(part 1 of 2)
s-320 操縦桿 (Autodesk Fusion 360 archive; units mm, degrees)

design "s-320 操縦桿" references "基板取付用2連ボリューム B10kΩ"
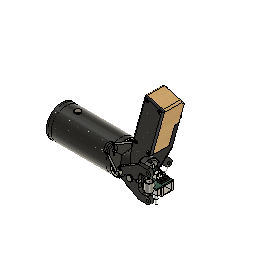
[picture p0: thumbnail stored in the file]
description: AWA10-30
part number: AWA10-30
description: SFBJ2.6-10
part number: SFBJ2.6-10
description: NPN1.6-10
part number: NPN1.6-10
description: HCLGN6-39.3_D
part number: HCLGN6-39.3_D
description: HCLGN6-39.3
part number: HCLGN6-39.3
description: NPN1-10
part number: NPN1-10
description: HCLGN4-8.2_D
part number: HCLGN4-8.2_D
description: HCLGN4-8.2
part number: HCLGN4-8.2
description: HCLGN6-16.0_D
part number: HCLGN6-16.0_D
parameter "d679" = 0.1
sketch "スケッチ1" plane through (0, 0, 0) normal (1, 0, 0) x axis (0, 1, 0)
  line L1 (0, -23.6) -> (0, 23.6)
  line L2 (-13.5196, -8.0798) -> (-45.6012, 45.6012)
  line L3 (8.0798, 13.5196) -> (-45.6012, 45.6012)
  line L4 (12.8728, -7.7) -> (12.8728, -6.1)
  line L5 (-12.8728, -7.7) -> (12.8728, -7.7)
  line L6 (-12.8728, -6.1) -> (-12.8728, -7.7)
  line L7 (12.8728, -6.1) -> (-12.8728, -6.1)
  line L8 (0, 0) -> (-26.7817, 26.7817)
  circle C1 centre (0, 0) radius 23.6
  circle C2 centre (0, 0) radius 23.5
  circle C3 centre (0, 0) radius 15
  circle C4 centre (0, 0) radius 15.75
  circle C5 centre (-26.7817, 26.7817) radius 6.5
  circle C6 centre (-26.7817, 26.7817) radius 3.5
  circle C7 centre (-26.7817, 26.7817) radius 2
  point P1 (0, 0)
  point P2 (0, 0)
  point P3 (0, 0)
  point P6 (0, 23.6)
  point P7 (0, -23.6)
  point P5 (0, 0)
  point P8 (0, 15.75)
  point P9 (0, 23.5)
  point P11 (-13.5196, -8.0798)
  point P17 (12.8728, -7.7)
  point P18 (-12.8728, -7.7)
  point P19 (-12.8728, -7.7)
  point P20 (12.8728, -7.7)
  point P13 (-26.7817, 26.7817)
  point P21 (-26.7817, 26.7817)
  point P4 (0, 0)
  point P22 (0, 0)
  point P16 (12.8728, -6.1)
  coincident P1 P2
  coincident P1 P3
  concentric C2 C3
  concentric C2 C4
  coincident C1 P6
  coincident C1 P7
  vertical L1
  coincident P5 L1
  coincident L1 P8
  coincident C4 P8
  coincident L1 P9
  coincident C2 P9
  tangent C4 L2
  tangent C4 L3
  equal L2 L3
  tangent L3 C5
  concentric C5 C6
  coincident C4 P11
  tangent L2 C5
  vertical L4
  horizontal L5
  vertical L6
  coincident C3 P17
  perpendicular L4 L7
  coincident C3 P18
  coincident P18 P19
  coincident P17 P20
  coincident P13 P21
  coincident P4 P22
  concentric C5 C7
  dimension "d7" diameter C2 = 47
  dimension "d8" distance C1 C2 = 0.1
  dimension "d9" diameter C3 = 30
  dimension "d10" distance C3 C4 = 0.75
  dimension "d22" diameter C6 = 7
  dimension "d23" distance C5 C6 = 3
  dimension "d27" angle P4 P9 P13 = 45
  dimension "d96" distance P16 P17 = 1.6
  dimension "d98" distance P4 L7 = 6.1
  dimension "d303" distance P21 P22 = 37.875
  dimension "d551" diameter C7 = 4
sketch "スケッチ4" plane through (0, 0, 0) normal (0, 1, 0) x axis (1, 0, 0)
  line L1 (-7, -23) -> (0, -23)
  line L2 (-7, -21.6024) -> (0, -21.6024)
  line L3 (-7, -16.6722) -> (-7, -23)
  line L4 (-6.5, -16.6722) -> (-7, -16.6722)
  line L5 (-6.5, -17.8066) -> (-6.5, -16.6722)
  line L6 (-6, -17.8066) -> (-6.5, -17.8066)
  line L7 (-6, -19.1283) -> (-6, -17.8066)
  line L8 (-6.5, -19.1283) -> (-6, -19.1283)
  line L9 (-6.5, -19.7045) -> (-6.5, -19.1283)
  line L10 (-6, -19.7045) -> (-6.5, -19.7045)
  line L11 (-6, -21.0261) -> (-6, -19.7045)
  line L12 (-7, -21.0261) -> (-6, -21.0261)
  line L13 (-7, -21.6024) -> (-7, -21.0261)
  line L14 (0, -16.6722) -> (0, -23)
  line L15 (-0.5, -16.6722) -> (0, -16.6722)
  line L16 (-0.5, -17.8066) -> (-0.5, -16.6722)
  line L17 (-1, -17.8066) -> (-0.5, -17.8066)
  line L18 (-1, -19.1283) -> (-1, -17.8066)
  line L19 (-0.5, -19.1283) -> (-1, -19.1283)
  line L20 (-0.5, -19.7045) -> (-0.5, -19.1283)
  line L21 (-1, -19.7045) -> (-0.5, -19.7045)
  line L22 (-1, -21.0261) -> (-1, -19.7045)
  line L23 (0, -21.0261) -> (-1, -21.0261)
  line L24 (0, -21.6024) -> (0, -21.0261)
  line L25 (-3.5, -21.6024) -> (-3.5, -23)
  line L26 (0, 23.6) -> (0, -23.6)
  line L27 (-7, -15.75) -> (-7, -21.6024)
  line L28 (0, -15.75) -> (-7, -15.75)
  point P28 (-3.5, -23)
  point P29 (-3.5, -21.6024)
  point P7 (0, -15.75)
  point P33 (0, -15.75)
  point P2 (0, -23)
  point P3 (-7, -23)
  point P6 (0, -23.5)
  horizontal L1
  horizontal L2
  equal L1 L2
  perpendicular L1 L3
  perpendicular L3 L4
  perpendicular L4 L5
  perpendicular L5 L6
  perpendicular L6 L7
  perpendicular L5 L8
  perpendicular L8 L9
  perpendicular L9 L10
  perpendicular L10 L11
  perpendicular L11 L12
  perpendicular L1 L14
  perpendicular L14 L15
  perpendicular L15 L16
  perpendicular L16 L17
  perpendicular L17 L18
  perpendicular L16 L19
  perpendicular L17 L20
  perpendicular L20 L21
  perpendicular L21 L22
  perpendicular L22 L23
  midpoint L1 P28
  midpoint L2 P29
  symmetric L4 L15 L25
  symmetric L6 L17 L25
  symmetric L5 L16 L25
  symmetric L7 L18 L25
  symmetric L8 L19 L25
  symmetric L9 L20 L25
  symmetric L11 L22 L25
  symmetric L10 L21 L25
  symmetric L12 L23 L25
  equal L6 L8
  equal L8 L10
  equal L7 L11
  equal L9 L13
  perpendicular L12 L13
  equal L4 L6
  perpendicular L2 L24
  collinear L24 L26
  perpendicular L2 L27
  coincident P7 P33
  perpendicular L27 L28
  dimension "d11" distance P2 P3 = 7
  dimension "d12" distance L7 L25 = 2.5
  dimension "d665" distance P2 P6 = 0.5
revolve "回転" sketch "スケッチ4" AlongAngle 360
extrude "押し出し5" new body sketch "スケッチ1" profile of C1 C2 C4 L2 L3 C5 C6 along normal blind 3
sketch "スケッチ6" plane through (0, 0, 0) normal (-1, 0, 0) x axis (0, -1, 0)
  line L1 (-23.2254, 1.0696) -> (-24.0956, -17.8259)
  line L2 (1.0696, -23.2254) -> (-17.8259, -24.0956)
  line L3 (-18.1019, -18.1019) -> (26.7817, 26.7817)
  circle C1 centre (-18.1019, -18.1019) radius 6
  circle C2 centre (0, 0) radius 23.25
  circle C3 centre (0, 0) radius 23
  circle C4 centre (-18.1019, -18.1019) radius 2
  circle C5 centre (0, 0) radius 23.5
  circle C6 centre (0, 0) radius 23.6
  circle C7 centre (0, 0) radius 21.0261
  point P4 (-24.0956, -17.8259)
  point P6 (-17.8259, -24.0956)
  point P5 (-23.2254, 1.0696)
  point P7 (1.0696, -23.2254)
  point P13 (0, 0)
  point P9 (-18.1019, -18.1019)
  point P12 (-18.1019, -18.1019)
  point P11 (26.7817, 26.7817)
  point P15 (26.7817, 26.7817)
  coincident C1 P4
  coincident C1 P6
  tangent C1 L2
  tangent C2 L2
  tangent C1 L1
  tangent C2 L1
  coincident C2 P5
  coincident C2 P7
  concentric C1 C4
  coincident L3 P13
  tangent C4 C6
  coincident P9 P12
  coincident P11 P15
  dimension "d281" diameter C1 = 12
  dimension "d282" diameter C4 = 4
extrude "押し出し11" new body sketch "スケッチ6" profile of C1 C2 L1 L2 C4 C6 along normal blind 5
sketch "スケッチ5" plane through (3, 0, 0) normal (1, 0, 0) x axis (0, 1, 0)
  line L1 (-23.4471, 32.3612) -> (8.0798, 13.5196)
  line L2 (-13.5196, -8.0798) -> (-32.3612, 23.4472)
  line L3 (-22.1855, 22.1855) -> (-31.247, 31.247)
  line L4 (8.074, 19.1147) -> (-24.2525, 32.7694)
  line L5 (-19.1147, -8.074) -> (-32.7694, 24.2525)
  line L6 (61.3359, -28.8089) -> (35.7796, -3.2527)
  line L7 (28.8089, -61.3359) -> (3.2527, -35.7796)
  line L8 (35.88, -54.2648) -> (54.2648, -35.88)
  line L9 (10.3238, -28.7085) -> (35.88, -54.2648)
  line L10 (28.7085, -10.3238) -> (10.3238, -28.7085)
  line L11 (54.2648, -35.88) -> (28.7085, -10.3238)
  line L12 (14.9765, -17.8049) -> (18.1019, -20.9304)
  line L13 (17.8049, -14.9765) -> (20.9304, -18.1019)
  line L14 (18.1019, -18.1019) -> (-26.7817, 26.7817)
  line L15 (-14.5382, 14.5382) -> (-1.3727, 15.6901)
  line L16 (-15.6901, 1.3727) -> (-14.5382, 14.5382)
  line L17 (14.5382, -14.5382) -> (1.3727, -15.6901)
  line L18 (14.5382, -14.5382) -> (15.6901, -1.3727)
  line L19 (13.4687, 15.7847) -> (35.7796, -3.2527)
  line L20 (-15.7847, -13.4687) -> (3.2527, -35.7796)
  arc A1 centre (-26.7817, 26.7817) radius 6.5 clockwise from (-32.3612, 23.4472) to (-23.4471, 32.3612)
  arc A2 centre (0, 0) radius 15.75 clockwise from (-13.5196, -8.0798) to (8.0798, 13.5196)
  circle C1 centre (-26.7817, 26.7817) radius 2
  circle C2 centre (-26.7817, 26.7817) radius 6.5
  circle C3 centre (0, 0) radius 15.75
  circle C4 centre (0, 0) radius 20.75
  circle C5 centre (32.3445, -57.8003) radius 5
  circle C6 centre (57.8003, -32.3445) radius 5
  circle C7 centre (18.1019, -18.1019) radius 2
  circle C8 centre (0, 0) radius 15
  circle C9 centre (16.3907, -16.3907) radius 2
  circle C10 centre (-26.7817, 26.7817) radius 3.5
  circle C11 centre (57.8003, -32.3445) radius 2
  circle C12 centre (32.3445, -57.8003) radius 2
  circle C13 centre (-26.7817, 26.7817) radius 3.5
  point P4 (-23.4471, 32.3612)
  point P11 (-22.1855, 22.1855)
  point P8 (-26.7817, 26.7817)
  point P1 (0, 0)
  point P13 (0, 0)
  point P14 (-24.2525, 32.7694)
  point P15 (8.074, 19.1147)
  point P17 (-19.1147, -8.074)
  point P16 (-32.7694, 24.2525)
  point P19 (61.3359, -28.8089)
  point P21 (28.8089, -61.3359)
  point P28 (18.1019, -18.1019)
  point P30 (18.1019, -18.1019)
  point P34 (17.8049, -14.9765)
  point P32 (14.9765, -17.8049)
  point P39 (-1.3727, 15.6901)
  point P40 (-14.5382, 14.5382)
  point P41 (-15.6901, 1.3727)
  point P42 (1.3727, -15.6901)
  point P43 (14.5382, -14.5382)
  point P44 (15.6901, -1.3727)
  point P33 (20.9304, -18.1019)
  point P31 (18.1019, -20.9304)
  point P24 (54.2648, -35.88)
  point P25 (35.88, -54.2648)
  point P49 (13.4687, 15.7847)
  point P50 (-15.7847, -13.4687)
  point P37 (16.3907, -16.3907)
  point P45 (0, 0)
  point P22 (32.3445, -57.8003)
  point P47 (57.8003, -32.3445)
  concentric C1 C2
  coincident P4 C2
  coincident C2 P11
  coincident P8 L3
  coincident P1 P13
  tangent C4 L4
  tangent C2 L4
  coincident C2 P14
  coincident C4 P15
  tangent C4 L5
  coincident C4 P17
  tangent C2 L5
  coincident C2 P16
  parallel L3 L6
  parallel L3 L7
  coincident P19 C6
  coincident P21 C5
  tangent L6 C6
  equal C5 C6
  equal L6 L7
  perpendicular L8 L9
  perpendicular L9 L10
  perpendicular L10 L11
  tangent C5 L9
  tangent C6 L11
  tangent L7 C5
  coincident P28 P30
  tangent C7 L12
  tangent C7 L13
  parallel L12 L14
  tangent L10 C7
  tangent L13 C9
  tangent L12 C9
  coincident P34 C9
  coincident P32 C9
  coincident C3 P39
  coincident L14 P40
  coincident C3 P41
  equal L15 L16
  tangent C3 L15
  coincident C3 P42
  coincident L14 P43
  tangent C3 L17
  coincident C3 P44
  tangent C3 L18
  equal L15 L18
  coincident L10 P33
  coincident L10 P31
  concentric C1 C10
  perpendicular L10 L12
  parallel L6 L11
  coincident C6 P24
  concentric C6 C11
  concentric C5 C12
  equal C11 C12
  coincident C5 P25
  equal L6 L11
  coincident C4 P49
  coincident C4 P50
  equal L19 L20
  tangent C4 L20
  tangent C4 L19
  parallel L12 L13
  dimension "d29" distance C3 C4 = 5
  dimension "d30" diameter C1 = 4
  dimension "d46" diameter C6 = 10
  dimension "d54" diameter C7 = 4
  dimension "d288" angle L15 L16 = 100
  dimension "d302" distance P37 P45 = 23.18
  dimension "d304" distance L8 P30 = 38.142
  dimension "d338" diameter C11 = 4
  dimension "d632" distance P22 P47 = 36
extrude "押し出し6" new body sketch "スケッチ5" profile of A1 C1 C2 L14 C10 along normal blind 2.5
extrude "押し出し7" add sketch "スケッチ5" profile of L1 A1 A2 C2 C3 C4 L4 L6 C6 L10 L11 L13 L14 C9 L15 L18 C11 L19 along normal blind 5
extrude "押し出し8" new body of existing geometry blind 2.5
extrude "押し出し9" add sketch "スケッチ5" profile of A1 L2 A2 C2 C3 C4 L5 L7 C5 L9 L10 L12 L14 C9 L16 L17 C12 L20 along normal blind 5
fillet "フィレット1" radius 5
work_plane "作業平面2" RotateAngle 0 RotateAngle 0
sketch "スケッチ14" plane through (0, 0, -6.1) normal (0, 0, 1) x axis (1, 0, 0)
  line L1 (-82.5, -12.8728) -> (59.5, -12.8728)
  line L2 (-82.5, 12.8728) -> (-82.5, -12.8728)
  line L3 (59.5, 12.8728) -> (-82.5, 12.8728)
  line L4 (59.5, -12.8728) -> (59.5, 12.8728)
  line L5 (9, -10.5) -> (-68, -10.5)
  line L6 (9, 10.5) -> (9, -10.5)
  line L7 (-68, 10.5) -> (9, 10.5)
  line L8 (-68, -10.5) -> (-68, 10.5)
  line L9 (9, 12.8728) -> (9, -12.8728)
  line L10 (5.75, 9) -> (-64.75, 9)
  line L11 (5.75, -9) -> (5.75, 9)
  line L12 (-64.75, -9) -> (5.75, -9)
  line L13 (-64.75, 9) -> (-64.75, -9)
  line L14 (-64.75, 10.5) -> (-64.75, 9)
  line L15 (-64.75, -10.5) -> (-64.75, -9)
  line L16 (5.75, 10.5) -> (5.75, 9)
  line L17 (5.75, -10.5) -> (5.75, -9)
  line L18 (-72.9, 2.5) -> (-68, 2.5)
  line L19 (-72.9, -2.5) -> (-72.9, 2.5)
  line L20 (-68, -2.5) -> (-72.9, -2.5)
  line L21 (-82.5, 4.75) -> (-72.9, 4.75)
  line L22 (-82.5, -4.75) -> (-82.5, 4.75)
  line L23 (-72.9, -4.75) -> (-82.5, -4.75)
  line L24 (-72.9, 4.75) -> (-72.9, -4.75)
  line L25 (-68, -2.5) -> (-68, 2.5)
  line L26 (13.9, -2.5) -> (9, -2.5)
  line L27 (13.9, 2.5) -> (13.9, -2.5)
  line L28 (9, 2.5) -> (13.9, 2.5)
  line L29 (9, -2.5) -> (9, 2.5)
  line L30 (22.5, 12.8728) -> (22.5, -12.8728)
  line L31 (36.5, -3.7272) -> (27, -3.7272)
  line L32 (36.5, 5.8728) -> (36.5, -3.7272)
  line L33 (27, 5.8728) -> (36.5, 5.8728)
  line L34 (27, -3.7272) -> (27, 5.8728)
  line L35 (59.5, 12.8728) -> (38.5, 12.8728)
  line L36 (59.5, -5.1272) -> (59.5, 12.8728)
  line L37 (38.5, -5.1272) -> (59.5, -5.1272)
  line L38 (38.5, 12.8728) -> (38.5, -5.1272)
  line L39 (59.5, 10.3728) -> (38.5, 10.3728)
  line L40 (38.5, -2.6272) -> (59.5, -2.6272)
  line L41 (24.5, 12.8728) -> (22.5, 12.8728)
  line L42 (22.5, -12.8728) -> (24.5, -12.8728)
  line L43 (22.5, 12.8728) -> (22.5, -12.8728)
  line L44 (12, 12.8728) -> (12, -12.8728)
  line L45 (51.3, -6.45) -> (59.5, -6.45)
  line L46 (51.3, -11.55) -> (51.3, -6.45)
  line L47 (59.5, -11.55) -> (51.3, -11.55)
  line L48 (47.5, -1.0872) -> (47.5, 8.8328)
  line L49 (41.6, -1.0872) -> (47.5, -1.0872)
  line L50 (41.6, 8.8328) -> (41.6, -1.0872)
  line L51 (47.5, 8.8328) -> (41.6, 8.8328)
  line L52 (46.7, -0.2872) -> (46.7, 8.0328)
  line L53 (42.4, -0.2872) -> (46.7, -0.2872)
  line L54 (42.4, 8.0328) -> (42.4, -0.2872)
  line L55 (46.7, 8.0328) -> (42.4, 8.0328)
  line L56 (46.7, 6.4328) -> (47.5, 6.4328)
  line L57 (46.7, 1.3128) -> (47.5, 1.3128)
  line L58 (51.2, -11.875) -> (51.2, -6.125)
  line L59 (36.25, -11.875) -> (51.2, -11.875)
  line L60 (36.25, -6.125) -> (36.25, -11.875)
  line L61 (51.2, -6.125) -> (36.25, -6.125)
  line L62 (56.5, 10.1228) -> (50.5, 10.1228)
  line L63 (56.5, 4.1228) -> (56.5, 10.1228)
  line L64 (50.5, 4.1228) -> (56.5, 4.1228)
  line L65 (50.5, 10.1228) -> (50.5, 4.1228)
  line L66 (56.5, 3.6228) -> (50.5, 3.6228)
  line L67 (56.5, -2.3772) -> (56.5, 3.6228)
  line L68 (50.5, -2.3772) -> (56.5, -2.3772)
  line L69 (50.5, 3.6228) -> (50.5, -2.3772)
  line L70 (37.05, -6.925) -> (37.05, -11.075)
  line L71 (50.4, -6.925) -> (37.05, -6.925)
  line L72 (50.4, -11.075) -> (50.4, -6.925)
  line L73 (37.05, -11.075) -> (50.4, -11.075)
  line L74 (50.5, 10.1228) -> (56.5, 4.1228)
  line L75 (56.5, -2.3772) -> (50.5, 3.6228)
  line L76 (38.15, -11.075) -> (38.15, -11.875)
  line L77 (49.3, -11.075) -> (49.3, -11.875)
  line L78 (39.7, -11.075) -> (39.7, -11.875)
  line L79 (47.75, -11.875) -> (47.75, -11.075)
  line L80 (46.7, 2.4628) -> (47.5, 2.4628)
  line L81 (47.5, 5.2828) -> (46.7, 5.2828)
  line L82 (59.5, -6.45) -> (59.5, -11.55)
  line L83 (59.5, -5.1272) -> (59.5, -12.8728)
  line L84 (51.2, -5.1272) -> (51.2, -12.8728)
  line L85 (38.5, 3.8728) -> (59.5, 3.8728)
  line L86 (56.5, 4.1228) -> (56.5, 3.6228)
  line L87 (51.2, -9) -> (51.3, -9)
  circle C1 centre (53.5, 7.1228) radius 1.7
  circle C2 centre (53.5, 0.6228) radius 1.7
  circle C3 centre (51.25, -9) radius 2.65
  point P6 (0, -12.8728)
  point P7 (0, 12.8728)
  point P13 (9, -12.8728)
  point P14 (9, 12.8728)
  point P19 (-64.75, 10.5)
  point P20 (-64.75, -10.5)
  point P21 (5.75, 10.5)
  point P22 (5.75, -10.5)
  point P31 (9, -2.5)
  point P35 (22.5, -12.8728)
  point P36 (22.5, 12.8728)
  point P45 (38.5, 10.3728)
  point P46 (59.5, 10.3728)
  point P47 (59.5, -2.6272)
  point P48 (38.5, -2.6272)
  point P50 (24.5, -12.8728)
  point P52 (12, -12.8728)
  point P53 (12, 12.8728)
  point P64 (47.5, 6.4328)
  point P65 (46.7, 6.4328)
  point P66 (47.5, 1.3128)
  point P67 (46.7, 1.3128)
  point P80 (43.725, -6.125)
  point P81 (53.5, 7.1228)
  point P82 (53.5, 0.6228)
  point P87 (38.15, -11.875)
  point P88 (38.15, -11.075)
  point P89 (49.3, -11.875)
  point P90 (49.3, -11.075)
  point P91 (39.7, -11.875)
  point P92 (39.7, -11.075)
  point P93 (47.75, -11.075)
  point P94 (47.75, -11.875)
  point P95 (47.5, 2.4628)
  point P96 (46.7, 2.4628)
  point P97 (46.7, 5.2828)
  point P98 (47.5, 5.2828)
  point P102 (51.2, -12.8728)
  point P103 (51.2, -5.1272)
  point P104 (59.5, 3.8728)
  point P105 (38.5, 3.8728)
  point P106 (56.5, 3.8728)
  point P107 (47.5, 3.8728)
  point P108 (51.3, -9)
  point P109 (51.2, -9)
  point P99 (51.25, -9)
  point P10 (9, 10.5)
  point P11 (-68, 10.5)
  point P8 (-68, -10.5)
  point P29 (-82.5, -4.75)
  point P30 (-72.9, -4.75)
  point P28 (-82.5, 4.75)
  point P25 (-72.9, -2.5)
  point P26 (-68, -2.5)
  point P39 (36.5, 5.8728)
  point P40 (27, 5.8728)
  point P38 (36.5, -3.7272)
  point P42 (59.5, 12.8728)
  point P43 (59.5, -5.1272)
  point P41 (38.5, 12.8728)
  point P57 (47.5, -1.0872)
  point P58 (41.6, -1.0872)
  point P59 (41.6, 8.8328)
  point P69 (51.2, -11.875)
  point P70 (36.25, -11.875)
  point P71 (36.25, -6.125)
  point P72 (50.5, 10.1228)
  point P73 (56.5, 10.1228)
  point P75 (50.5, 4.1228)
  point P100 (59.5, -6.45)
  point P101 (59.5, -11.55)
  point P54 (51.3, -6.45)
  point P74 (56.5, 4.1228)
  point P77 (56.5, 3.6228)
  horizontal L1
  vertical L2
  horizontal L3
  vertical L4
  coincident L1 P6
  coincident L3 P7
  horizontal L5
  vertical L6
  horizontal L7
  vertical L8
  coincident L1 P13
  coincident L3 P14
  perpendicular L3 L9
  midpoint L6 L9
  horizontal L10
  vertical L11
  horizontal L12
  vertical L13
  coincident L7 P19
  perpendicular L7 L14
  coincident L5 P20
  perpendicular L5 L15
  coincident L7 P21
  perpendicular L7 L16
  coincident L5 P22
  perpendicular L5 L17
  horizontal L18
  vertical L19
  horizontal L20
  horizontal L21
  vertical L22
  horizontal L23
  vertical L24
  midpoint L19 L24
  perpendicular L20 L25
  midpoint L8 L25
  horizontal L26
  vertical L27
  horizontal L28
  vertical L29
  coincident L9 P31
  equal L25 L27
  equal L20 L26
  midpoint L9 L29
  coincident L1 P35
  coincident L3 P36
  perpendicular L3 L30
  horizontal L31
  vertical L32
  horizontal L33
  vertical L34
  horizontal L35
  vertical L36
  horizontal L37
  vertical L38
  coincident L38 P45
  coincident L36 P46
  perpendicular L36 L39
  coincident L36 P47
  coincident L38 P48
  perpendicular L38 L40
  horizontal L41
  horizontal L42
  vertical L43
  coincident L1 P50
  coincident L1 P52
  coincident L3 P53
  perpendicular L3 L44
  horizontal L45
  vertical L46
  horizontal L47
  coincident L48 P64
  coincident L52 P65
  perpendicular L52 L56
  coincident L48 P66
  coincident L52 P67
  perpendicular L52 L57
  horizontal L62
  vertical L63
  horizontal L64
  vertical L65
  horizontal L66
  vertical L67
  horizontal L68
  vertical L69
  equal L62 L66
  equal L65 L69
  midpoint L61 P80
  equal C1 C2
  midpoint P81 L74
  midpoint P82 L75
  coincident L59 P87
  coincident L73 P88
  perpendicular L73 L76
  coincident L59 P89
  coincident L73 P90
  perpendicular L73 L77
  coincident L59 P91
  coincident L73 P92
  perpendicular L73 L78
  coincident L73 P93
  coincident L59 P94
  perpendicular L59 L79
  coincident L48 P95
  coincident L52 P96
  perpendicular L52 L80
  coincident L52 P97
  coincident L48 P98
  perpendicular L48 L81
  perpendicular L47 L82
  collinear L3 L35
  collinear L4 L36
  midpoint L82 L83
  parallel L71 L73
  coincident L1 P102
  coincident L37 P103
  perpendicular L37 L84
  midpoint L58 L84
  collinear L58 L84
  parallel L52 L54
  midpoint L36 P104
  midpoint L38 P105
  collinear L63 L67
  midpoint L86 P106
  coincident L85 P106
  midpoint L48 P107
  coincident L85 P107
  midpoint L46 P108
  midpoint L84 P109
  midpoint P99 L87
  dimension "d100" distance P10 P11 = 77
  dimension "d101" distance P8 P11 = 21
  dimension "d111" distance P6 L9 = 9
  dimension "d112" distance L7 L10 = 1.5
  dimension "d113" distance L5 L12 = 1.5
  dimension "d114" distance L6 L11 = 3.25
  dimension "d115" distance L8 L13 = 3.25
  dimension "d129" distance P29 P30 = 9.6
  dimension "d130" distance P28 P29 = 9.5
  dimension "d131" distance P25 P26 = 4.9
  dimension "d132" distance L18 L20 = 5
  dimension "d141" distance L9 L30 = 13.5
  dimension "d157" distance P39 P40 = 9.5
  dimension "d158" distance P38 P39 = 9.6
  dimension "d159" distance P42 P43 = 18
  dimension "d160" distance P41 P42 = 21
  dimension "d161" distance L37 L40 = 2.5
  dimension "d162" distance L35 L39 = 2.5
  dimension "d186" distance L9 L44 = 3
  dimension "d195" distance P57 P58 = 5.9
  dimension "d196" distance P58 P59 = 9.92
  dimension "d197" distance L51 L55 = 0.8
  dimension "d198" distance L48 L52 = 0.8
  dimension "d199" distance L49 L53 = 0.8
  dimension "d200" distance L50 L54 = 0.8
  dimension "d233" distance L3 L33 = 7
  dimension "d447" distance L51 L56 = 2.4
  dimension "d448" distance L49 L57 = 2.4
  dimension "d553" distance P69 P70 = 14.95
  dimension "d554" distance P70 P71 = 5.75
  dimension "d555" distance P72 P73 = 6
  dimension "d556" distance P72 P75 = 6
  dimension "d559" distance L60 L70 = 0.8
  dimension "d560" distance L61 L71 = 0.8
  dimension "d561" distance L58 L72 = 0.8
  dimension "d562" distance L59 L73 = 0.8
  dimension "d563" diameter C1 = 3.4
  dimension "d564" distance L60 L76 = 1.9
  dimension "d565" distance L58 L77 = 1.9
  dimension "d567" distance L58 L79 = 3.45
  dimension "d568" distance L60 L78 = 3.45
  dimension "d569" distance L49 L80 = 3.55
  dimension "d570" distance L51 L81 = 3.55
  dimension "d571" diameter C3 = 5.3
  dimension "d634" distance P100 P101 = 5.1
  dimension "d635" distance P54 P100 = 8.2
  dimension "d637" distance L32 L38 = 2
  dimension "d638" distance L36 L67 = 3
  dimension "d639" distance L48 L69 = 3
  dimension "d640" distance P74 P77 = 0.5
  dimension "d641" distance L46 L84 = 0.1
  dimension "d695" distance L30 L34 = 4.5
extrude "押し出し22" new body sketch "スケッチ14" profile of L1 L2 L3 L4 L5 L6 L7 L8 L9 to an object
sketch "スケッチ15" plane through (0, 12.8728, 0) normal (0, 1, 0) x axis (-1, 0, 0)
  line L1 (82.5, -7.7) -> (-59.5, -7.7)
  line L2 (82.5, -6.1) -> (82.5, -7.7)
  line L3 (-59.5, -6.1) -> (82.5, -6.1)
  line L4 (-59.5, -7.7) -> (-59.5, -6.1)
  line L5 (-9, 0) -> (-21, 0)
  line L6 (-9, -6.1) -> (-9, 0)
  line L7 (-21, -6.1) -> (-9, -6.1)
  line L8 (-21, 0) -> (-21, -6.1)
  line L9 (0, 0) -> (-9, 0)
  circle C1 centre (-15, 0) radius 3.25
  circle C2 centre (-15, 0) radius 6
  point P8 (-9, -6.1)
  point P10 (-9, -6.1)
  point P11 (-15, 0)
  point P7 (-9, 0)
  point P9 (-21, -6.1)
  point P13 (-21, -6.1)
  point P15 (0, 0)
  point P6 (-21, 0)
  horizontal L5
  vertical L6
  horizontal L7
  vertical L8
  coincident P8 P10
  midpoint L5 P11
  concentric C1 C2
  coincident P7 C2
  coincident P9 P13
  perpendicular L6 L9
  coincident L9 P15
  dimension "d107" diameter C1 = 6.5
  dimension "d108" distance P6 P7 = 12
extrude "押し出し24" new body sketch "スケッチ14" profile of L10 L11 L12 L13 along normal blind 1
extrude "押し出し25" add sketch "スケッチ14" profile of L5 L7 L10 L12 L14 L15 L16 L17 along normal blind 11
extrude "押し出し26" add sketch "スケッチ14" profile of L5 L6 L7 L8 L9 L11 L13 L14 L15 L16 L17 along normal blind 20.3
sketch "スケッチ16" plane through (-64.75, 0, 0) normal (1, 0, 0) x axis (0, 1, 0)
  line L1 (-9, 4.9) -> (-10.5, 4.9)
  line L2 (-9, -5.1) -> (-9, 4.9)
  line L3 (9, -5.1) -> (-9, -5.1)
  line L4 (9, 4.9) -> (9, -5.1)
  line L5 (10.5, 4.9) -> (9, 4.9)
  line L6 (10.5, 14.2) -> (10.5, 4.9)
  line L7 (-10.5, 14.2) -> (10.5, 14.2)
  line L8 (-10.5, 4.9) -> (-10.5, 14.2)
  line L9 (-5.5, 14.2) -> (-10.5, 4.9)
  line L10 (5.5, 14.2) -> (10.5, 4.9)
  point P2 (-10.5, 4.9)
  point P10 (-10.5, 4.9)
  point P11 (-5.5, 14.2)
  point P7 (10.5, 4.9)
  point P12 (10.5, 4.9)
  point P13 (5.5, 14.2)
  coincident P2 P10
  coincident L7 P11
  coincident P7 P12
  coincident L7 P13
  equal L9 L10
  dimension "d122" distance P11 P13 = 11
extrude "押し出し27" cut sketch "スケッチ16" profile of L6 L7 L8 L9 L10 no distance stored
fillet "フィレット2" radius 2
extrude "押し出し28" add sketch "スケッチ14" profile of L6 L8 L9 L18 L19 L20 L24 L25 L26 L27 L28 L29 along normal blind 1
component_insert "コンポーネントの挿入14"
extrude "押し出し30" new body sketch "スケッチ15" profile of L3 L5 L6 L7 L8 C1 C2 to an object
extrude "押し出し31" cut sketch "スケッチ14" profile of L6 L9 L26 L27 L28 L29 L44 along normal blind 2
extrude "押し出し35" new body sketch "スケッチ1" profile of C3 C4 to an object
extrude "押し出し36" new body sketch "スケッチ1" profile of C1 C2 L2 L3 C5 to an object
extrude "押し出し39" new body sketch "スケッチ5" profile of C7 to an object Side2Offset 0
extrude "押し出し40" sketch "スケッチ14" profile of L3 L4 L35 L36 L37 L38 L39 L40 blind -11 bodies "ESP32"
extrude "押し出し41" sketch "スケッチ14" profile of L3 L4 L35 L36 L37 L38 L39 L40 L48 L49 L50 L51 L52 L53 L54 L55 L56 L57 L62 L63 L64 L65 L66 L67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 blind -1
sketch "スケッチ17" plane through (-97.5, 0, 0) normal (-1, 0, 0) x axis (0, -1, 0)
  line L1 (2.5981, -1.5) -> (-2.5981, -1.5)
  circle C1 centre (0, 0) radius 23.5
  circle C2 centre (0, 0) radius 23.6
  circle C3 centre (0, 0) radius 23
  circle C4 centre (0, 0) radius 23.5
  circle C5 centre (0, 0) radius 3
  arc A1 centre (0, 0) radius 3 clockwise from (-2.5981, -1.5) to (2.5981, -1.5)
  circle C6 centre (0, 0) radius 23
  point P1 (0, 0)
  point P3 (0, 0)
  point P7 (-2.5981, -1.5)
  point P9 (-2.5981, -1.5)
  point P6 (2.5981, -1.5)
  point P10 (2.5981, -1.5)
  coincident P1 P3
  concentric C3 C5
  equal C5 A1
  horizontal L1
  coincident P7 P9
  coincident P6 P10
  equal C3 C6
extrude "押し出し42" sketch "スケッチ17" profile of C3 C5 A1 L1 C6 blind 5
extrude "押し出し46" sketch "スケッチ14" profile of L4 L45 L46 L47 blind -8.2
sketch "スケッチ18" plane through (0, 0, -15.9) normal (0, 0, -1) x axis (-1, 0, 0)
  line L1 (-51.3, -11.55) -> (-59.5, -11.55)
  line L2 (-59.5, -11.55) -> (-59.5, -6.45)
  line L3 (-59.5, -6.45) -> (-51.3, -6.45)
  line L4 (-51.3, -6.45) -> (-51.3, -11.55)
  line L5 (-59.5, -11.55) -> (-59.5, -11.55)
  line L6 (-51.3, -6.45) -> (-59.5, -11.55)
  circle C1 centre (-55.4, -9) radius 2.35
  circle C2 centre (-55.4, -9) radius 1.85
  circle C3 centre (-55.4, -9) radius 1.05
  point P4 (-59.5, -11.55)
  point P7 (-59.5, -11.55)
  point P2 (-59.5, -11.55)
  point P8 (-59.5, -11.55)
  point P13 (-59.5, -11.55)
  point P12 (-51.3, -6.45)
  point P14 (-51.3, -6.45)
  point P9 (-55.4, -9)
  coincident P4 P7
  coincident P2 P8
  concentric C1 C2
  concentric C2 C3
  coincident P4 P13
  coincident P12 P14
  midpoint P9 L6
  dimension "d216" diameter C1 = 4.7
  dimension "d217" distance C1 C2 = 0.5
  dimension "d220" diameter C3 = 2.1
extrude "押し出し50" add sketch "スケッチ18" profile of C1 C2 blind 5.8
extrude "押し出し51" add sketch "スケッチ18" profile of C3 blind 15
extrude "押し出し47" new body sketch "スケッチ14" profile of L48 L49 L50 L51 L52 L53 L54 L55 L56 L57 L80 L81 along normal blind 7.1 bodies "XH"
extrude "押し出し48" add sketch "スケッチ14" profile of L52 L53 L54 L55 along normal blind 1
extrude "押し出し49" add sketch "スケッチ14" profile of L48 L49 L50 L51 L52 L53 L54 L55 L56 L57 L80 L81 along normal blind 3.2
extrude "押し出し110" sketch "スケッチ14" profile of L58 L59 L60 L61 L70 L71 L72 L73 L76 L77 L78 L79 blind -7.1 bodies "XH3"
extrude "押し出し111" sketch "スケッチ14" profile of L59 L73 L76 L77 L78 L79 blind -3.2
extrude "押し出し112" sketch "スケッチ14" profile of L58 L59 L60 L61 L70 L71 L72 L73 L76 L77 L78 L79 blind -1
extrude "押し出し113" new body sketch "スケッチ14" profile of L62 L63 L64 L65 L66 L67 L68 L69 C1 C2 along normal blind 2.95
extrude "押し出し114" sketch "スケッチ14" profile of C1 C2 blind 5
extrude "押し出し115" new body sketch "スケッチ14" profile of L64 L66 C1 C2 C3 along normal blind 8.7 bodies "LED"
fillet "フィレット5" radius 2.5
fillet "フィレット3" radius 1
component_insert "コンポーネントの挿入23"
position "位置5"
work_plane "作業平面4" AlongDistance 1
extrude "押し出し52" add sketch "スケッチ1" profile of C3 C4 to an object
extrude "押し出し98" cut of existing geometry blind -2
extrude "押し出し70" cut sketch "スケッチ15" profile of L5 C1 no distance stored
extrude "押し出し56" new body sketch "スケッチ15" profile of L5 C1 along normal blind 3 and against normal blind 42
sketch "スケッチ19" plane through (0, 15.8728, 0) normal (0, 1, 0) x axis (-1, 0, 0)
  circle C1 centre (-15, 0) radius 3.25
  circle C2 centre (-15, 0) radius 4.5
  concentric C1 C2
  dimension "d241" diameter C2 = 9
extrude "押し出し57" add sketch "スケッチ19" along normal blind 1.5
sketch "スケッチ25" plane through (36, 0, 0) normal (1, 0, 0) x axis (0, 1, 0)
  line L1 (-8.7272, -6.1) -> (-8.7272, 12.1999)
  line L2 (-13.7036, -6.1) -> (-8.7272, -6.1)
  line L3 (-5.1272, -6.1) -> (12.8728, -6.1)
  line L4 (-3.7272, 5.2) -> (-3.7272, -6.1)
  circle C1 centre (0, 0) radius 15
  point P4 (-13.7036, -6.1)
  point P2 (-8.7272, 12.1999)
  vertical L1
  perpendicular L1 L2
  coincident P4 C1
  coincident P2 C1
  collinear L2 L3
  dimension "d314" distance L1 L4 = 5
extrude "押し出し69" new body sketch "スケッチ25" profile of L1 L2 C1 to an object offset 3
sketch "スケッチ26" plane through (0, -8.7272, 0) normal (0, 1, 0) x axis (-1, 0, 0)
  line L1 (-24, 12.1999) -> (-24, -6.1)
  line L2 (-36, 12.1999) -> (-24, 12.1999)
  line L3 (-36, -6.1) -> (-36, 12.1999)
  line L4 (-24, -6.1) -> (-36, -6.1)
  line L5 (-30.25, 3.25) -> (-36, 3.25)
  line L6 (-36, -3.25) -> (-30.25, -3.25)
  line L7 (-36, -6.1) -> (-36, 12.1999)
  circle C1 centre (-30.25, 0) radius 3.25
  arc A1 centre (-30.25, 0) radius 3 clockwise from (-32.8481, -1.5) to (-27.6519, -1.5)
  point P10 (-36, 3.25)
  point P11 (-30.25, 3.25)
  point P13 (-36, -3.25)
  point P12 (-30.25, -3.25)
  concentric C1 A1
  perpendicular L3 L5
  perpendicular L3 L6
  coincident P10 L7
  coincident C1 P11
  coincident P13 L7
  coincident C1 P12
  tangent C1 L6
  tangent C1 L5
  dimension "d730" diameter C1 = 6.5
extrude "押し出し71" cut sketch "スケッチ26" profile of C1 A1 blind 0
extrude "押し出し120" cut sketch "スケッチ26" profile of L3 C1 A1 L5 L6 L7 no distance stored
work_plane "作業平面3" AlongDistance -17.75
sketch "スケッチ27" plane through (0, -17.75, 0) normal (0, 1, 0) x axis (1, 0, 0)
  line L1 (55.667, -23) -> (42.417, -23)
  line L2 (42.417, -13) -> (55.667, -13)
  line L3 (55.667, 13) -> (42.417, 13)
  line L4 (55.667, 23) -> (42.417, 23)
  line L5 (42.417, 13) -> (42.417, -13)
  line L6 (11.9691, -5.1782) -> (42.417, -23)
  line L7 (11.9691, 5.1782) -> (42.417, 23)
  line L8 (27.7604, -2.0891) -> (26.0074, 0)
  line L9 (34.4926, 0) -> (32.7396, -2.0891)
  line L10 (26.0074, 0) -> (27.7604, 2.0891)
  line L11 (34.4926, 0) -> (32.7396, 2.0891)
  line L12 (42.417, 0) -> (21, 0)
  line L13 (39.583, -2) -> (42.417, -2)
  line L14 (39.583, 2) -> (42.417, 2)
  line L15 (40.9088, 4.9758) -> (30.8401, 5.9709)
  line L16 (30.8401, -5.9709) -> (40.9088, -4.9758)
  line L17 (46.528, -114.8261) -> (26.4851, -42.5538)
  line L18 (75.4369, -106.8089) -> (46.528, -114.8261)
  line L19 (55.394, -34.5366) -> (75.4369, -106.8089)
  line L20 (26.4851, -42.5538) -> (55.394, -34.5366)
  line L21 (30.25, 0) -> (60.9824, -110.8175)
  line L22 (24.2583, -0.3159) -> (26.4851, -42.5538)
  line L23 (35.5486, 2.8152) -> (55.394, -34.5366)
  line L24 (19.2306, 10.0286) -> (30.25, 0)
  line L25 (15.6926, 3.1753) -> (30.25, 0)
  line L26 (28.0686, 16.8936) -> (35.5486, 2.8152)
  circle C1 centre (40.417, 0) radius 2
  circle C2 centre (15, 0) radius 6
  circle C3 centre (55.667, -18) radius 5
  circle C4 centre (55.667, 18) radius 5
  circle C5 centre (39.583, 0) radius 2
  circle C6 centre (30.25, 0) radius 3.25
  circle C7 centre (30.25, 0) radius 3.25
  circle C8 centre (55.667, -18) radius 2
  circle C9 centre (55.667, 18) radius 2
  circle C10 centre (40.417, 0) radius 5
  circle C11 centre (30.25, 0) radius 6
  circle C12 centre (15, 0) radius 3.25
  circle C13 centre (15, 0) radius 3.25
  circle C14 centre (8.7979, -1.4348) radius 15.5
  circle C15 centre (23.0532, 14.2288) radius 5.6793
  point P14 (11.9691, -5.1782)
  point P15 (11.9691, 5.1782)
  point P25 (21, 0)
  point P26 (42.417, 0)
  point P7 (55.667, -23)
  point P8 (55.667, -13)
  point P11 (55.667, 13)
  point P13 (55.667, 23)
  point P2 (40.417, 0)
  point P24 (39.583, 0)
  point P18 (32.7396, -2.0891)
  point P22 (32.7396, 2.0891)
  point P20 (27.7604, 2.0891)
  point P17 (27.7604, -2.0891)
  point P16 (26.0074, 0)
  point P21 (26.0074, 0)
  point P19 (34.4926, 0)
  point P23 (34.4926, 0)
  point P3 (15, 0)
  point P29 (15, 0)
  point P30 (42.417, -2)
  point P32 (42.417, 2)
  point P31 (39.583, -2)
  point P33 (39.583, 2)
  point P38 (30.8401, 5.9709)
  point P39 (40.9088, 4.9758)
  point P40 (40.9088, -4.9758)
  point P41 (30.8401, -5.9709)
  point P46 (60.9824, -110.8175)
  point P27 (30.25, 0)
  point P47 (30.25, 0)
  point P48 (24.2583, -0.3159)
  point P49 (35.5486, 2.8152)
  point P53 (15.6926, 3.1753)
  point P52 (19.2306, 10.0286)
  point P56 (35.5486, 2.8152)
  point P57 (28.0686, 16.8936)
  point P4 (55.667, -18)
  point P42 (26.4851, -42.5538)
  point P45 (55.394, -34.5366)
  point P37 (30.25, 0)
  point P34 (55.667, -18)
  point P35 (55.667, 18)
  horizontal L1
  horizontal L2
  horizontal L3
  horizontal L4
  coincident C2 P14
  coincident C2 P15
  parallel L9 L10
  coincident C2 P25
  coincident L5 P26
  horizontal L12
  tangent C3 L1
  tangent C3 L2
  tangent C4 L3
  tangent C4 L4
  equal C3 C4
  coincident C3 P7
  coincident C3 P8
  coincident C4 P11
  coincident C4 P13
  vertical L5
  tangent C1 L5
  midpoint L5 P26
  coincident P2 L12
  coincident P24 L12
  equal C1 C5
  concentric C6 C7
  equal C6 C7
  coincident P18 C6
  coincident P22 C6
  coincident P20 C6
  coincident P17 C6
  coincident P16 P21
  coincident P21 L12
  coincident P19 P23
  coincident P19 L12
  tangent L8 C6
  tangent L9 C6
  tangent L11 C6
  tangent L10 C6
  equal L8 L9
  coincident P3 P29
  equal L1 L2
  equal L2 L3
  equal L3 L4
  equal L6 L7
  coincident L5 P30
  coincident L5 P32
  coincident C5 P31
  coincident C5 P33
  tangent C1 L14
  tangent C5 L14
  tangent C1 L13
  tangent C5 L13
  tangent C2 L6
  concentric C3 C8
  concentric C4 C9
  concentric C1 C10
  concentric C6 C11
  coincident C11 P38
  coincident C10 P39
  coincident C10 P40
  coincident C11 P41
  tangent C10 L15
  tangent C10 L16
  tangent C11 L16
  tangent C11 L15
  perpendicular L17 L18
  perpendicular L18 L19
  perpendicular L19 L20
  midpoint L18 P46
  coincident P27 P47
  perpendicular L18 L21
  tangent C11 L22
  tangent C11 L23
  coincident C11 P48
  coincident C11 P49
  concentric C2 C12
  equal C12 C13
  equal C8 C9
  coincident C13 P53
  tangent C13 L25
  coincident C12 P53
  equal L24 L25
  coincident P52 C14
  tangent C11 C14
  tangent L24 C14
  coincident C11 P56
  coincident C15 P57
  tangent C15 L26
  tangent C14 C15
  coincident P52 C15
  tangent C11 L26
  collinear L23 L26
  dimension "d322" angle L8 L10 = 100
  dimension "d324" distance L1 L2 = 10
  dimension "d329" diameter C1 = 4
  dimension "d334" distance P2 P27 = 10.167
  dimension "d335" distance P24 P27 = 9.333
  dimension "d336" distance P2 P4 = 15.25
  dimension "d337" diameter C2 = 12
  dimension "d340" diameter C8 = 4
  dimension "d342" diameter C10 = 10
  dimension "d343" diameter C11 = 12
  dimension "d344" distance P42 P45 = 30
  dimension "d346" angle L12 L21 = 74.5
  dimension "d347" distance P37 L20 = 40
  dimension "d348" distance L18 L20 = 75
  dimension "d631" distance P34 P35 = 36
  dimension "d662" angle L24 L25 = 30
extrude "押し出し72" new body sketch "スケッチ27" profile of C2 C12 C13 against normal blind 2.5
extrude "押し出し73" new body sketch "スケッチ27" profile of C2 C3 L1 L2 L5 L6 L8 L9 C5 L12 C6 C7 L13 C8 C10 C11 L16 L21 L22 L23 C14 against normal blind 5
extrude "押し出し74" new body of existing geometry blind 2.5
extrude "押し出し75" new body sketch "スケッチ27" profile of C2 C4 L3 L4 L5 L7 L10 L11 C5 L12 C6 C7 L14 C9 C10 C11 L15 L23 C14 C15 L26 against normal blind 5
combine "結合1"
combine "結合2"
fillet "フィレット4" radius 5
work_plane "作業平面5" AlongDistance 17.75
sketch "スケッチ28" plane through (0, 17.75, 0) normal (0, 1, 0) x axis (1, 0, 0)
extrude "押し出し76" new body sketch "スケッチ27" profile of C1 L1 L2 L5 L6 L7 L8 L9 L10 L11 C5 L12 C6 C7 L13 L14 C10 C11 L15 L16 L17 L18 L19 L20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 along normal blind 2
extrude "押し出し77" sketch "スケッチ27" profile of L1 L2 L5 L6 L8 L9 L10 L11 L12 C6 C7 C10 C11 L16 L17 L18 L19 L20 L21 L22 L23 C14 blind -2
extrude "押し出し78" sketch "スケッチ27" profile of L17 L18 L19 L21 to an object
sketch "スケッチ45" plane through (42.5441, 0, -11.7985) normal (0.9636, 0, -0.2672) x axis (0, 1, 0)
  line L1 (15.75, 123.084) -> (15.75, 48.084)
  line L2 (-15.75, 123.084) -> (15.75, 123.084)
  line L3 (-15.75, 48.084) -> (-15.75, 123.084)
  line L4 (15.75, 48.084) -> (-15.75, 48.084)
  circle C1 centre (17.75, 123.084) radius 7.5
  point P6 (17.75, 123.084)
  point P7 (17.75, 123.084)
  coincident P6 P7
  dimension "d659" diameter C1 = 15
extrude "押し出し123" cut sketch "スケッチ45" profile of L1 L2 C1 to an object
extrude "押し出し80" cut of existing geometry to an object
sketch "スケッチ44" plane through (0, 17.75, 0) normal (0, 1, 0) x axis (-1, 0, 0)
  line L1 (-32.8481, -1.5) -> (-27.6519, -1.5)
  line L2 (-26.4851, 42.5538) -> (-24.2583, 0.3159)
  line L3 (-44.5237, 107.5988) -> (-26.4851, 42.5538)
  line L4 (-55.394, 34.5366) -> (-73.4326, 99.5817)
  line L5 (-35.5486, -2.8152) -> (-55.394, 34.5366)
  line L6 (-16.3279, -4.2996) -> (-30.25, 0)
  line L7 (-20.3429, -10.6846) -> (-30.25, 0)
  line L8 (-24.1533, -1.6763) -> (-24.2583, 0.3159)
  line L9 (-28.3449, -16.3735) -> (-35.5486, -2.8152)
  line L10 (-73.4326, 99.5817) -> (-44.5237, 107.5988)
  arc A1 centre (-30.25, 0) radius 3 clockwise from (-32.8481, -1.5) to (-27.6519, -1.5)
  arc A2 centre (-30.25, 0) radius 6 clockwise from (-24.2583, 0.3159) to (-35.5486, -2.8152)
  circle C1 centre (-15, 0) radius 4.5
  circle C2 centre (-9.8122, -0.9203) radius 14.3611
  circle C3 centre (-23.9731, -14.0507) radius 4.9506
  point P4 (-30.25, 0)
  point P11 (-30.25, 0)
  point P12 (-16.3279, -4.2996)
  point P5 (-24.2583, 0.3159)
  point P16 (-24.2583, 0.3159)
  point P17 (-24.1533, -1.6763)
  point P14 (-20.3429, -10.6846)
  point P19 (-35.5486, -2.8152)
  point P20 (-28.3449, -16.3735)
  coincident P4 P11
  tangent L6 C1
  coincident P12 C1
  tangent L2 C2
  tangent L7 C2
  coincident P5 P16
  tangent A2 L8
  coincident C2 P17
  tangent C2 L8
  equal L6 L7
  coincident P14 C2
  coincident P14 C3
  coincident A2 P19
  coincident C3 P20
  tangent C3 L9
  tangent A2 L9
  tangent L7 C3
  collinear L5 L9
  dimension "d655" angle L6 L7 = 30
extrude "押し出し122" add sketch "スケッチ44" profile of A2 C2 L8 C3 L9 to an object
extrude "押し出し81" new body sketch "スケッチ27" profile of C1 C5 L12 to an object Side2Offset 0
extrude "押し出し82" new body sketch "スケッチ26" profile of C1 A1 along normal blind 5 and against normal blind 16
sketch "スケッチ29" plane through (0, -24.7272, 0) normal (0, -1, 0) x axis (1, 0, 0)
  circle C1 centre (30.25, 0) radius 3.25
  circle C2 centre (30.25, 0) radius 4.5
  concentric C1 C2
  dimension "d382" diameter C2 = 9
extrude "押し出し83" add sketch "スケッチ29" along normal blind 1.5
sketch "スケッチ31" plane through (0, 17.75, 0) normal (0, 1, 0) x axis (-1, 0, 0)
  line L1 (-32.8481, -1.5) -> (-27.6519, -1.5)
  line L2 (-26.4851, 42.5538) -> (-24.1533, -1.6763)
  line L3 (-44.5237, 107.5988) -> (-26.4851, 42.5538)
  line L4 (-55.394, 34.5366) -> (-73.4326, 99.5817)
  line L5 (-28.3449, -16.3735) -> (-55.394, 34.5366)
  line L6 (-37.2076, 66.2501) -> (-46.2937, 99.0136)
  line L7 (-58.4075, 60.3709) -> (-37.2076, 66.2501)
  line L8 (-45.492, 96.1227) -> (-51.2738, 94.5193)
  line L9 (-43.8886, 90.3409) -> (-45.492, 96.1227)
  line L10 (-49.6704, 88.7375) -> (-43.8886, 90.3409)
  line L11 (-51.2738, 94.5193) -> (-49.6704, 88.7375)
  line L12 (-42.5524, 85.5228) -> (-48.3342, 83.9193)
  line L13 (-40.949, 79.741) -> (-42.5524, 85.5228)
  line L14 (-46.7307, 78.1375) -> (-40.949, 79.741)
  line L15 (-48.3342, 83.9193) -> (-46.7307, 78.1375)
  line L16 (-39.6128, 74.9228) -> (-45.3946, 73.3194)
  line L17 (-38.0093, 69.141) -> (-39.6128, 74.9228)
  line L18 (-43.7911, 67.5376) -> (-38.0093, 69.141)
  line L19 (-45.3946, 73.3194) -> (-43.7911, 67.5376)
  line L20 (-43.8886, 90.3409) -> (-51.2738, 94.5193)
  line L21 (-40.949, 79.741) -> (-48.3342, 83.9193)
  line L22 (-38.0093, 69.141) -> (-45.3946, 73.3194)
  line L23 (-30.25, 0) -> (-60.9824, 110.8175)
  line L24 (-75.4369, 106.8089) -> (-46.528, 114.8261)
  line L25 (-51.9082, 74.0555) -> (-61.4674, 71.4045)
  line L26 (-48.8483, 63.0219) -> (-51.9082, 74.0555)
  line L27 (-61.4674, 71.4045) -> (-58.4075, 60.3709)
  line L28 (-57.4439, 60.6381) -> (-60.5037, 71.6717)
  line L29 (-49.8119, 62.7547) -> (-52.8718, 73.7882)
  line L30 (-51.6826, 69.5001) -> (-59.3145, 67.3836)
  line L31 (-51.4153, 68.5364) -> (-59.0473, 66.4199)
  line L32 (-58.7923, 64.4152) -> (-57.7233, 60.5606)
  line L33 (-50.6014, 66.6867) -> (-58.7923, 64.4152)
  line L34 (-49.5325, 62.8322) -> (-50.6014, 66.6867)
  line L35 (-26.4851, 42.5538) -> (-55.394, 34.5366)
  line L36 (-35.5486, -2.8152) -> (-55.394, 34.5366)
  line L37 (-58.4075, 60.3709) -> (-67.4936, 93.1343)
  line L38 (-55.394, 34.5366) -> (-75.4369, 106.8089)
  line L39 (-24.2583, 0.3159) -> (-26.4851, 42.5538)
  line L40 (-54.6968, 65.5509) -> (-55.2313, 67.4782)
  line L41 (-58.7722, 84.1378) -> (-60.3756, 89.9196)
  line L42 (-64.554, 82.5344) -> (-58.7722, 84.1378)
  line L43 (-66.1574, 88.3162) -> (-64.554, 82.5344)
  line L44 (-60.3756, 89.9196) -> (-66.1574, 88.3162)
  line L45 (-58.7722, 84.1378) -> (-66.1574, 88.3162)
  line L46 (-46.2937, 99.0136) -> (-67.4936, 93.1343)
  line L47 (-56.5188, 60.8947) -> (-57.5877, 64.7492)
  line L48 (-51.806, 66.3526) -> (-50.737, 62.4981)
  line L49 (-26.4851, 42.5538) -> (-36.2207, 77.6593)
  line L50 (-26.4851, 42.5538) -> (-55.394, 34.5366)
  line L51 (-65.3219, 70.3355) -> (-61.4674, 71.4045)
  line L52 (-41.9803, 38.2566) -> (-48.8483, 63.0219)
  line L53 (-73.4326, 99.5817) -> (-44.5237, 107.5988)
  arc A1 centre (-30.25, 0) radius 3 clockwise from (-32.8481, -1.5) to (-27.6519, -1.5)
  circle C1 centre (-47.5812, 92.4301) radius 1.725
  circle C2 centre (-44.6416, 81.8301) radius 1.725
  circle C3 centre (-41.7019, 71.2302) radius 1.725
  circle C4 centre (-62.4648, 86.227) radius 1.725
  circle C5 centre (-59.181, 73.0763) radius 2.65
  arc A2 centre (-23.9731, -14.0507) radius 4.9506 clockwise from (-20.3429, -10.6846) to (-28.3449, -16.3735)
  arc A3 centre (-9.8122, -0.9203) radius 14.3611 clockwise from (-20.3429, -10.6846) to (-24.1533, -1.6763)
  point P24 (-47.5812, 92.4301)
  point P25 (-44.6416, 81.8301)
  point P26 (-41.7019, 71.2302)
  point P34 (-60.5037, 71.6717)
  point P35 (-57.4439, 60.6381)
  point P36 (-52.8718, 73.7882)
  point P38 (-59.3145, 67.3836)
  point P39 (-51.6826, 69.5001)
  point P40 (-59.0473, 66.4199)
  point P41 (-51.4153, 68.5364)
  point P45 (-49.5325, 62.8322)
  point P47 (-58.4075, 60.3709)
  point P54 (-58.4075, 60.3709)
  point P52 (-55.394, 34.5366)
  point P46 (-55.394, 34.5366)
  point P49 (-55.394, 34.5366)
  point P5 (-26.4851, 42.5538)
  point P48 (-26.4851, 42.5538)
  point P57 (-55.2313, 67.4782)
  point P58 (-54.6968, 65.5509)
  point P11 (-37.2076, 66.2501)
  point P53 (-37.2076, 66.2501)
  point P63 (-62.4648, 86.227)
  point P65 (-57.5877, 64.7492)
  point P68 (-51.806, 66.3526)
  point P69 (-36.2207, 77.6593)
  point P55 (-26.4851, 42.5538)
  point P70 (-26.4851, 42.5538)
  point P71 (-55.394, 34.5366)
  point P33 (-58.4075, 60.3709)
  point P42 (-57.7233, 60.5606)
  point P66 (-56.5188, 60.8947)
  point P67 (-50.737, 62.4981)
  point P37 (-49.8119, 62.7547)
  point P72 (-48.8483, 63.0219)
  point P73 (-65.3219, 70.3355)
  point P74 (-41.9803, 38.2566)
  point P13 (-45.492, 96.1227)
  point P14 (-43.8886, 90.3409)
  point P31 (-61.4674, 71.4045)
  point P32 (-51.9082, 74.0555)
  point P43 (-58.7923, 64.4152)
  point P44 (-50.6014, 66.6867)
  point P64 (-59.181, 73.0763)
  equal L11 L15
  equal L15 L19
  equal L12 L15
  equal L16 L19
  equal C1 C2
  equal C2 C3
  midpoint P24 L20
  midpoint P25 L21
  midpoint P26 L22
  coincident L25 P34
  coincident L7 P35
  coincident L25 P36
  coincident L28 P38
  coincident L29 P39
  perpendicular L29 L30
  coincident L28 P40
  coincident L29 P41
  perpendicular L29 L31
  perpendicular L32 L33
  coincident L7 P45
  perpendicular L6 L35
  equal L8 L9
  parallel L12 L14
  parallel L16 L18
  parallel L26 L27
  perpendicular L18 L37
  coincident P47 P54
  parallel L37 L38
  coincident L35 P52
  coincident P46 P49
  coincident P5 P48
  midpoint L31 P57
  midpoint L33 P58
  perpendicular L31 L40
  coincident P11 P53
  collinear L11 L15
  collinear L15 L19
  perpendicular L17 L18
  perpendicular L13 L14
  perpendicular L9 L10
  perpendicular L23 L42
  perpendicular L42 L43
  parallel L6 L41
  parallel L42 L44
  equal L10 L42
  equal L9 L41
  equal C1 C4
  midpoint P63 L45
  perpendicular L8 L11
  perpendicular L6 L46
  coincident L33 P65
  coincident L33 P68
  perpendicular L33 L48
  perpendicular L33 L47
  perpendicular L7 L37
  coincident L3 P69
  coincident P55 P70
  coincident P49 P71
  collinear L6 L13
  collinear L37 L43
  collinear L27 L37
  coincident L7 P33
  coincident L7 P42
  coincident L7 P66
  coincident L7 P67
  coincident L7 P37
  coincident L7 P72
  perpendicular L25 L37
  coincident L38 P73
  perpendicular L38 L51
  coincident L50 P74
  perpendicular L50 L52
  tangent L37 C5
  dimension "d386" distance L14 L16 = 5
  dimension "d387" distance L10 L12 = 5
  dimension "d388" distance P13 P14 = 6
  dimension "d389" diameter C1 = 3.45
  dimension "d393" distance P31 P32 = 9.92
  dimension "d394" distance L26 L29 = 1
  dimension "d395" distance L27 L28 = 1
  dimension "d399" distance L30 L31 = 1
  dimension "d423" distance L7 L30 = 7
  dimension "d424" distance L31 L33 = 2
  dimension "d425" distance P43 P44 = 8.5
  dimension "d468" distance L37 L38 = 4
  dimension "d605" distance L3 L6 = 4
  dimension "d606" diameter C5 = 5.3
  dimension "d608" distance L24 L46 = 15.3
  dimension "d623" distance L34 L48 = 1.25
  dimension "d624" distance L32 L47 = 1.25
  dimension "d626" distance L7 L18 = 3
  dimension "d644" distance L8 L46 = 3
  dimension "d645" distance P32 P72 = 11.45
  dimension "d646" distance L44 L46 = 5
  dimension "d647" distance L25 P64 = 1
extrude "押し出し84" cut sketch "スケッチ31" profile of L6 L7 L8 L9 L10 L11 L12 L13 L14 L15 L16 L17 L18 L19 C1 C2 C3 L23 L25 L26 L27 L28 L29 L30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 against normal blind 2.5
extrude "押し出し95" sketch "スケッチ31" profile of L6 L7 L8 L9 L10 L11 L12 L13 L14 L15 L16 L17 L18 L19 C1 C2 C3 L23 L25 L26 L27 L28 L29 L30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 blind 1.6
extrude "押し出し85" sketch "スケッチ31" profile of L6 L8 L9 L10 L11 L12 L13 L14 L15 L16 L17 L18 L19 C1 C2 C3 L37 L41 L42 L43 L44 C4 blind 3
extrude "押し出し86" sketch "スケッチ31" profile of C1 C2 C3 C4 blind 2
extrude "押し出し116" sketch "スケッチ31" profile of L23 C5 blind 8.7
fillet "フィレット6" radius 2.5
extrude "押し出し119" cut sketch "スケッチ31" profile of L4 L7 L25 L26 L27 L28 L29 L30 L31 L32 L33 L34 L37 L38 C5 L47 L48 L50 L51 L52 against normal blind 8.5
extrude "押し出し91" sketch "スケッチ31" profile of L7 L25 L26 L27 L28 L29 L30 L31 L32 L33 L34 blind -1 bodies "XH2"
extrude "押し出し92" sketch "スケッチ31" profile of L6 L7 L23 L25 L26 L27 L28 L29 L30 L31 blind -4
extrude "押し出し93" sketch "スケッチ31" profile of L7 L25 L26 L27 L28 L29 L30 L31 L32 L33 L34 L37 C5 L47 L48 blind -1
sketch "スケッチ33" plane through (38.6896, 0, -10.7296) normal (0.9636, 0, -0.2672) x axis (0, 1, 0)
  line L1 (15.75, 73.784) -> (9.75, 73.784)
  line L2 (9.75, 85.234) -> (15.75, 85.234)
  line L3 (15.75, 85.234) -> (15.75, 73.784)
  line L4 (9.75, 73.784) -> (9.75, 85.234)
  line L5 (10.75, 81.234) -> (13.75, 85.234)
  line L6 (9.75, 81.234) -> (10.75, 81.234)
  point P6 (13.75, 85.234)
  point P8 (9.75, 81.234)
  point P7 (10.75, 81.234)
  point P5 (15.75, 85.234)
  point P2 (9.75, 85.234)
  coincident L2 P6
  coincident L4 P8
  perpendicular L4 L6
  dimension "d443" distance P7 P8 = 1
  dimension "d444" distance P5 P6 = 2
  dimension "d445" distance P2 P8 = 4
extrude "押し出し94" cut sketch "スケッチ33" profile of L2 L4 L5 L6 along a picked direction no distance stored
